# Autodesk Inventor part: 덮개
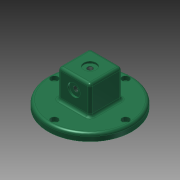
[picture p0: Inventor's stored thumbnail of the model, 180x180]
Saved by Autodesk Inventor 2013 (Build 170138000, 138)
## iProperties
Created: 2017-08
Part Number: 덮개
Material: 알루미늄 6061
Document SubType Name: Modeling
Designer: mduedu
Density: 1 g/cm^3
Author: mduedu
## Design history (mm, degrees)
sketch "스케치1"
  geometry: C1 r 47 at (0, 0); 1 further point
  constraints: 1 centre point, 1 coincident
  dimensions: "d55" = 94 diameter of C1
extrude "돌출1" new body sketch "스케치1" distance "d5" = 8; taper "d6" = 0 deg
sketch "스케치2"
  geometry: L1 (-18, -18)-(18, -18); L2 (18, -18)-(18, 18); L3 (18, 18)-(-18, 18); L4 (-18, 18)-(-18, -18); L5 (-18, -18)-(18, 18); L6 (18, -18)-(-18, 18); 1 further point
  constraints: 12 end point, 2 midpoint, 2 parallel, 2 perpendicular, 1 horizontal
  dimensions: "d7" = 36 distance of L2.end L3.end
extrude "돌출2" join sketch "스케치2" distance "d9" = 32; taper "d10" = 0 deg
sketch "스케치3"
  geometry: C1 r 35 at (0, 0); 1 further point
  constraints: 1 centre point, 1 coincident
  dimensions: "d56" = 70 diameter of C1
extrude "돌출3" join sketch "스케치3" distance "d12" = 6; taper "d13" = 0 deg
sketch "스케치4"
  geometry: C1 r 33 at (0, 0); 1 further point
  constraints: 1 centre point, 1 coincident
  dimensions: "d57" = 66 diameter of C1
extrude "돌출4" cut sketch "스케치4" distance "d16" = 5; taper "d17" = 0 deg
sketch "스케치5"
  geometry: C1 r 9 at (0, 0); 1 further point
  constraints: 1 centre point, 1 coincident
  dimensions: "d18" = 18 diameter of C1
extrude "돌출5" cut sketch "스케치5" distance "d19" = 34; taper "d20" = 0 deg
sketch "스케치6"
  geometry: 2 further points
  constraints: 1 coincident
hole "구멍1" sketch "스케치6" at (0, 0) diameter "d21" = 5.917; stored, may be unused: countersink angle "d25" = 90 deg, drill point angle "d27" = 118 deg; dims "d22" = 6, "d23" = 14, "d24" = 2, "d26" = 8
sketch "스케치7"
  geometry: L1 (-29, -8)-(65, -8) reference; 3 further points
  constraints: 1 midpoint, 1 vertical alignment
  dimensions: "d58" = 26 distance from line of point (18, 18) L1
hole "구멍2" sketch "스케치7" at (18, 18) diameter "d29" = 5.917; stored, may be unused: countersink angle "d33" = 90 deg, drill point angle "d35" = 118 deg; dims "d30" = 6, "d31" = 14, "d32" = 2, "d34" = 8
fillet "모깎기2" dims "d37" = 3
fillet "모깎기3" dims "d38" = 3
fillet "모깎기4" dims "d39" = 3
fillet "모깎기5" dims "d40" = 3
chamfer "모따기1" distance "d41" = 1; stored, may be unused: second distance "d42" = 2, angle "d43" = 45 deg
fillet "모깎기7" dims "d45" = 3
fillet "모깎기8" dims "d46" = 3
sketch "스케치10" dims "d59" = 80
  geometry: 3 further points
  constraints: 2 vertical alignment, 1 coincident, 2 other
hole "구멍4" sketch "스케치10" at (0, 40) diameter "d60" = 4.5; stored, may be unused: countersink angle "d64" = 90 deg, drill point angle "d66" = 118 deg; dims "d61" = 6, "d62" = 8, "d63" = 4.6, "d65" = 8
node "솔리드1"
pattern_circular "원형 패턴1" dims angle "d68" = 360 deg
